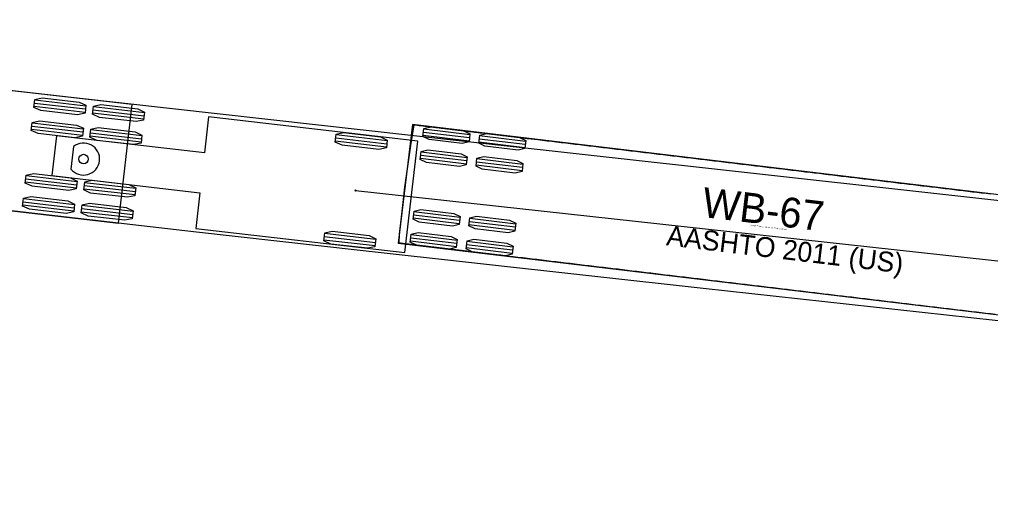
# Model space of a CAD drawing. Extents: x 2175591 to 2194071, y 76570 to 86955.
# Drawn here: x 2192687.6 to 2192756.8, y 86702.6 to 86737.7 of the extents above; entities that cross this region are included whole.
import ezdxf

# ---------------------------------------------------------------- set-up
doc = ezdxf.new("R2010")
doc.units = 0
doc.layers.add('-NOPLT', color=7, linetype='Continuous')
doc.layers.add('C-UTIL-STRM-TEXT', color=7, linetype='Continuous')

msp = doc.modelspace()

# ---------------------------------------------------------------- linework, layer by layer
at = {"layer": '-NOPLT'}
for p, q in [((2192715.586, 86730.244), (2192714.574, 86721.804)), ((2192768.209, 86723.935), (2192715.586, 86730.244)), ((2192719.652, 86729.294), (2192716.375, 86729.687)), ((2192719.679, 86729.522), (2192716.402, 86729.915)), ((2192719.624, 86729.067), (2192716.348, 86729.46)), ((2192723.596, 86728.591), (2192720.319, 86728.984)), ((2192723.623, 86728.818), (2192720.347, 86729.211)), ((2192723.651, 86729.046), (2192720.374, 86729.439)), ((2192719.483, 86727.884), (2192716.206, 86728.277)), ((2192719.428, 86727.429), (2192716.152, 86727.821)), ((2192719.455, 86727.656), (2192716.179, 86728.049)), ((2192723.427, 86727.18), (2192720.15, 86727.573)), ((2192723.454, 86727.408), (2192720.178, 86727.8)), ((2192723.4, 86726.953), (2192720.123, 86727.345)), ((2192718.918, 86723.176), (2192715.642, 86723.569)), ((2192718.945, 86723.403), (2192715.669, 86723.796)), ((2192718.973, 86723.631), (2192715.696, 86724.024)), ((2192722.944, 86723.155), (2192719.668, 86723.548)), ((2192722.89, 86722.7), (2192719.613, 86723.092)), ((2192722.917, 86722.927), (2192719.641, 86723.32)), ((2192718.749, 86721.765), (2192715.473, 86722.158)), ((2192718.776, 86721.993), (2192715.5, 86722.385)), ((2192714.574, 86721.804), (2192767.197, 86715.495)), ((2192718.722, 86721.538), (2192715.445, 86721.93)), ((2192722.693, 86721.061), (2192719.417, 86721.454)), ((2192722.721, 86721.289), (2192719.444, 86721.682)), ((2192722.748, 86721.516), (2192719.471, 86721.909))]:
    msp.add_line(p, q, dxfattribs=at)
for points in [[(2192757.089, 86716.707), (2192756.755, 86716.747), (2192756.421, 86716.787), (2192756.087, 86716.827), (2192755.753, 86716.867), (2192755.42, 86716.907), (2192755.087, 86716.947), (2192754.754, 86716.987), (2192754.421, 86717.027), (2192754.089, 86717.067), (2192753.756, 86717.107), (2192753.425, 86717.146), (2192753.093, 86717.186), (2192752.763, 86717.226), (2192752.432, 86717.265), (2192752.102, 86717.305), (2192751.772, 86717.345), (2192751.442, 86717.384), (2192751.113, 86717.424), (2192750.784, 86717.463), (2192750.455, 86717.502), (2192750.127, 86717.542), (2192749.799, 86717.581), (2192749.471, 86717.62), (2192749.144, 86717.66), (2192748.816, 86717.699), (2192748.489, 86717.738), (2192748.162, 86717.777), (2192747.835, 86717.817), (2192747.508, 86717.856), (2192747.181, 86717.895), (2192746.854, 86717.934), (2192746.527, 86717.973), (2192746.2, 86718.012), (2192745.873, 86718.052), (2192745.546, 86718.091), (2192745.218, 86718.13), (2192744.891, 86718.169), (2192744.563, 86718.209), (2192744.236, 86718.248), (2192743.908, 86718.287), (2192743.58, 86718.327), (2192743.252, 86718.366), (2192742.923, 86718.405), (2192742.594, 86718.445), (2192742.266, 86718.484), (2192741.936, 86718.524), (2192741.607, 86718.563), (2192741.277, 86718.603), (2192740.947, 86718.642), (2192740.616, 86718.682), (2192740.285, 86718.722), (2192739.954, 86718.761), (2192739.622, 86718.801), (2192739.29, 86718.841), (2192738.958, 86718.881), (2192738.624, 86718.921), (2192738.291, 86718.961), (2192737.957, 86719.001), (2192737.623, 86719.041), (2192737.289, 86719.081), (2192736.954, 86719.121), (2192736.618, 86719.161), (2192736.283, 86719.201), (2192735.947, 86719.242), (2192735.611, 86719.282), (2192735.274, 86719.322), (2192734.937, 86719.363), (2192734.6, 86719.403), (2192734.263, 86719.444), (2192733.926, 86719.484), (2192733.588, 86719.524), (2192733.25, 86719.565), (2192732.913, 86719.605), (2192732.575, 86719.646), (2192732.237, 86719.686), (2192731.899, 86719.727), (2192731.561, 86719.768), (2192731.223, 86719.808), (2192730.884, 86719.849), (2192730.546, 86719.889), (2192730.208, 86719.93), (2192729.87, 86719.97), (2192729.532, 86720.011), (2192729.194, 86720.051), (2192728.856, 86720.092), (2192728.517, 86720.132), (2192728.179, 86720.173), (2192727.841, 86720.213), (2192727.503, 86720.254), (2192727.165, 86720.295), (2192726.826, 86720.335), (2192726.488, 86720.376), (2192726.15, 86720.416), (2192725.812, 86720.457), (2192725.473, 86720.497), (2192725.135, 86720.538), (2192724.797, 86720.578), (2192724.458, 86720.619), (2192724.12, 86720.66), (2192723.782, 86720.7), (2192723.443, 86720.741), (2192723.105, 86720.781), (2192722.767, 86720.822), (2192722.155, 86720.895), (2192721.881, 86720.928), (2192721.607, 86720.961), (2192721.333, 86720.994), (2192721.059, 86721.027), (2192720.785, 86721.059), (2192720.511, 86721.092), (2192720.237, 86721.125), (2192719.964, 86721.158), (2192719.69, 86721.191), (2192719.472, 86721.217), (2192719.373, 86721.229), (2192719.275, 86721.24), (2192719.176, 86721.252), (2192719.077, 86721.264), (2192718.978, 86721.276), (2192718.88, 86721.288), (2192718.781, 86721.3), (2192718.682, 86721.311), (2192718.584, 86721.323), (2192718.485, 86721.335), (2192718.386, 86721.347), (2192718.288, 86721.359), (2192718.189, 86721.371), (2192718.09, 86721.382), (2192717.992, 86721.394), (2192717.893, 86721.406), (2192717.794, 86721.418), (2192717.696, 86721.43), (2192717.597, 86721.442), (2192717.498, 86721.453), (2192717.4, 86721.465), (2192717.301, 86721.477), (2192717.203, 86721.489), (2192717.104, 86721.501), (2192717.005, 86721.512), (2192716.907, 86721.524), (2192716.808, 86721.536), (2192716.71, 86721.548), (2192716.611, 86721.56), (2192716.513, 86721.572), (2192716.414, 86721.583), (2192716.316, 86721.595), (2192716.217, 86721.607), (2192716.119, 86721.619), (2192716.02, 86721.631), (2192715.922, 86721.642), (2192715.823, 86721.654), (2192715.725, 86721.666), (2192715.626, 86721.678), (2192715.528, 86721.69), (2192715.429, 86721.701), (2192715.331, 86721.713), (2192715.232, 86721.725), (2192715.134, 86721.737), (2192715.036, 86721.749), (2192714.937, 86721.76), (2192714.839, 86721.772), (2192714.742, 86721.788), (2192714.645, 86721.807), (2192714.661, 86722.435), (2192714.851, 86724.056), (2192714.951, 86724.915), (2192715.052, 86725.774), (2192715.269, 86727.259), (2192715.486, 86728.744), (2192715.703, 86730.229)], [(2192715.703, 86730.229), (2192715.821, 86730.215), (2192715.945, 86730.2), (2192716.073, 86730.185), (2192716.203, 86730.17), (2192716.333, 86730.154), (2192716.463, 86730.138), (2192716.594, 86730.123), (2192716.724, 86730.107), (2192716.855, 86730.091), (2192716.985, 86730.076), (2192717.116, 86730.06), (2192717.247, 86730.044), (2192717.377, 86730.029), (2192717.508, 86730.013), (2192717.639, 86729.997), (2192717.77, 86729.982), (2192717.902, 86729.966), (2192718.033, 86729.95), (2192718.164, 86729.934), (2192718.296, 86729.919), (2192718.427, 86729.903), (2192718.559, 86729.887), (2192718.691, 86729.871), (2192718.822, 86729.856), (2192718.954, 86729.84), (2192719.086, 86729.824), (2192719.218, 86729.808), (2192719.351, 86729.792), (2192719.483, 86729.776), (2192719.615, 86729.76), (2192719.748, 86729.745), (2192719.88, 86729.729), (2192720.013, 86729.713), (2192720.146, 86729.697), (2192720.278, 86729.681), (2192720.411, 86729.665), (2192720.544, 86729.649), (2192720.677, 86729.633), (2192720.811, 86729.617), (2192720.944, 86729.601), (2192721.077, 86729.585), (2192721.211, 86729.569), (2192721.344, 86729.553), (2192721.478, 86729.537), (2192721.612, 86729.521), (2192721.746, 86729.505), (2192721.88, 86729.489), (2192722.014, 86729.473), (2192722.148, 86729.457), (2192722.282, 86729.441), (2192722.416, 86729.425), (2192722.551, 86729.409), (2192722.697, 86729.391), (2192722.849, 86729.373), (2192723.001, 86729.355), (2192723.152, 86729.336), (2192723.303, 86729.318), (2192723.453, 86729.3), (2192723.603, 86729.282), (2192723.753, 86729.264), (2192723.903, 86729.246), (2192724.052, 86729.229), (2192724.531, 86729.171), (2192724.862, 86729.132), (2192725.192, 86729.092), (2192725.523, 86729.052), (2192725.853, 86729.013), (2192726.184, 86728.973), (2192726.515, 86728.933), (2192726.845, 86728.894), (2192727.176, 86728.854), (2192727.506, 86728.814), (2192727.837, 86728.775), (2192728.168, 86728.735), (2192728.498, 86728.696), (2192728.829, 86728.656), (2192729.159, 86728.616), (2192729.49, 86728.577), (2192729.82, 86728.537), (2192730.15, 86728.497), (2192730.481, 86728.458), (2192730.811, 86728.418), (2192731.142, 86728.379), (2192731.472, 86728.339), (2192731.803, 86728.299), (2192732.133, 86728.26), (2192732.463, 86728.22), (2192732.794, 86728.181), (2192733.124, 86728.141), (2192733.455, 86728.101), (2192733.785, 86728.062), (2192734.115, 86728.022), (2192734.445, 86727.983), (2192734.775, 86727.943), (2192735.105, 86727.903), (2192735.435, 86727.864), (2192735.765, 86727.824), (2192736.094, 86727.785), (2192736.424, 86727.745), (2192736.753, 86727.706), (2192737.082, 86727.667), (2192737.41, 86727.627), (2192737.739, 86727.588), (2192738.067, 86727.548), (2192738.394, 86727.509), (2192738.721, 86727.47), (2192739.048, 86727.431), (2192739.375, 86727.392), (2192739.701, 86727.352), (2192740.027, 86727.313), (2192740.352, 86727.274), (2192740.677, 86727.235), (2192741.002, 86727.197), (2192741.326, 86727.158), (2192741.65, 86727.119), (2192741.973, 86727.08), (2192742.296, 86727.041), (2192742.619, 86727.003), (2192742.941, 86726.964), (2192743.263, 86726.925), (2192743.585, 86726.887), (2192743.906, 86726.848), (2192744.227, 86726.81), (2192744.548, 86726.771), (2192744.869, 86726.733), (2192745.19, 86726.694), (2192745.51, 86726.656), (2192745.83, 86726.618), (2192746.15, 86726.579), (2192746.47, 86726.541), (2192746.79, 86726.503), (2192747.11, 86726.464), (2192747.429, 86726.426), (2192747.749, 86726.388), (2192748.068, 86726.349), (2192748.388, 86726.311), (2192748.707, 86726.273), (2192749.027, 86726.234), (2192749.347, 86726.196), (2192749.666, 86726.158), (2192749.986, 86726.119), (2192750.306, 86726.081), (2192750.626, 86726.043), (2192750.946, 86726.004), (2192751.267, 86725.966), (2192751.588, 86725.927), (2192751.909, 86725.889), (2192752.23, 86725.85), (2192752.552, 86725.812), (2192752.874, 86725.773), (2192753.196, 86725.735), (2192753.519, 86725.696), (2192753.842, 86725.657), (2192754.165, 86725.618), (2192754.489, 86725.58), (2192754.813, 86725.541), (2192755.138, 86725.502), (2192755.463, 86725.463), (2192755.788, 86725.424), (2192756.113, 86725.385), (2192756.439, 86725.346), (2192756.765, 86725.307)]]:
    msp.add_lwpolyline(points, dxfattribs=at)
for points in [[(2192719.686, 86729.578), (2192719.618, 86729.011), (2192719.138, 86728.894), (2192716.779, 86729.177), (2192716.341, 86729.403), (2192716.409, 86729.971), (2192716.888, 86730.087), (2192719.248, 86729.805)], [(2192723.657, 86729.102), (2192723.589, 86728.534), (2192723.11, 86728.418), (2192720.751, 86728.701), (2192720.313, 86728.927), (2192720.381, 86729.495), (2192720.86, 86729.611), (2192723.219, 86729.328)], [(2192719.489, 86727.94), (2192719.421, 86727.372), (2192718.942, 86727.256), (2192716.583, 86727.539), (2192716.145, 86727.765), (2192716.213, 86728.333), (2192716.692, 86728.449), (2192719.051, 86728.166)], [(2192723.461, 86727.464), (2192723.393, 86726.896), (2192722.914, 86726.78), (2192720.555, 86727.063), (2192720.116, 86727.289), (2192720.184, 86727.857), (2192720.664, 86727.973), (2192723.023, 86727.69)], [(2192718.98, 86723.687), (2192718.911, 86723.119), (2192718.432, 86723.003), (2192716.073, 86723.286), (2192715.635, 86723.512), (2192715.703, 86724.08), (2192716.182, 86724.196), (2192718.541, 86723.913)], [(2192722.951, 86723.211), (2192722.883, 86722.643), (2192722.404, 86722.527), (2192720.045, 86722.81), (2192719.606, 86723.036), (2192719.675, 86723.604), (2192720.154, 86723.72), (2192722.513, 86723.437)], [(2192718.783, 86722.049), (2192718.715, 86721.481), (2192718.236, 86721.365), (2192715.877, 86721.648), (2192715.439, 86721.874), (2192715.507, 86722.442), (2192715.986, 86722.558), (2192718.345, 86722.275)], [(2192722.755, 86721.573), (2192722.687, 86721.005), (2192722.207, 86720.889), (2192719.848, 86721.172), (2192719.41, 86721.398), (2192719.478, 86721.966), (2192719.957, 86722.082), (2192722.316, 86721.799)]]:
    msp.add_lwpolyline(points, close=True, dxfattribs=at)
at = {"layer": 'C-UTIL-STRM-TEXT'}
for p, q in [((2192695.635, 86731.665), (2192642.984, 86737.74)), ((2192692.308, 86731.336), (2192688.666, 86731.756)), ((2192692.335, 86731.563), (2192688.692, 86731.984)), ((2192692.282, 86731.108), (2192688.64, 86731.528)), ((2192696.454, 86730.627), (2192692.812, 86731.047)), ((2192696.481, 86730.854), (2192692.838, 86731.275)), ((2192696.507, 86731.082), (2192692.864, 86731.502)), ((2192694.661, 86723.221), (2192695.635, 86731.665)), ((2192695.635, 86731.665), (2192695.635, 86731.665)), ((2192692.146, 86729.924), (2192688.503, 86730.345)), ((2192701.07, 86730.786), (2192700.776, 86728.237)), ((2192715.971, 86729.067), (2192701.07, 86730.786)), ((2192692.093, 86729.469), (2192688.451, 86729.889)), ((2192692.119, 86729.697), (2192688.477, 86730.117)), ((2192696.292, 86729.215), (2192692.649, 86729.636)), ((2192696.318, 86729.443), (2192692.675, 86729.863)), ((2192642.01, 86729.296), (2192694.661, 86723.221)), ((2192690.245, 86729.452), (2192689.917, 86726.604)), ((2192700.776, 86728.237), (2192690.245, 86729.452)), ((2192696.265, 86728.988), (2192692.623, 86729.408)), ((2192713.74, 86728.633), (2192710.097, 86729.053)), ((2192713.766, 86728.86), (2192710.124, 86729.28)), ((2192713.792, 86729.088), (2192710.15, 86729.508)), ((2192715.054, 86721.12), (2192715.971, 86729.067)), ((2192715.971, 86729.067), (2192715.971, 86729.067)), ((2192691.457, 86728.682), (2192691.272, 86727.077)), ((2192691.686, 86725.938), (2192688.043, 86726.359)), ((2192691.712, 86726.166), (2192688.069, 86726.586)), ((2192689.917, 86726.604), (2192700.447, 86725.389)), ((2192691.659, 86725.711), (2192688.017, 86726.131)), ((2192695.832, 86725.229), (2192692.189, 86725.65)), ((2192695.858, 86725.457), (2192692.215, 86725.877)), ((2192695.884, 86725.685), (2192692.242, 86726.105)), ((2192711.539, 86725.552), (2192896.881, 86705.206)), ((2192691.523, 86724.527), (2192687.88, 86724.947)), ((2192700.447, 86725.389), (2192700.153, 86722.839)), ((2192691.47, 86724.072), (2192687.828, 86724.492)), ((2192691.497, 86724.299), (2192687.854, 86724.719)), ((2192695.669, 86723.818), (2192692.026, 86724.238)), ((2192695.695, 86724.045), (2192692.053, 86724.466)), ((2192695.643, 86723.59), (2192692, 86724.01)), ((2192700.153, 86722.839), (2192715.054, 86721.12)), ((2192712.954, 86721.824), (2192709.312, 86722.244)), ((2192712.98, 86722.051), (2192709.338, 86722.471)), ((2192712.928, 86721.596), (2192709.285, 86722.016))]:
    msp.add_line(p, q, dxfattribs=at)
for points in [[(2192881.867, 86702.593), (2192736.29, 86718.562), (2192712.089, 86721.246), (2192699.991, 86722.61), (2192642.01, 86729.296), (2192642.984, 86737.74), (2192643.16, 86737.719), (2192643.16, 86737.719)], [(2192643.16, 86737.719), (2192667.317, 86734.938), (2192691.501, 86732.186), (2192715.689, 86729.468), (2192764.077, 86724.094)]]:
    msp.add_lwpolyline(points, dxfattribs=at)
for points in [[(2192692.341, 86731.62), (2192692.276, 86731.052), (2192691.746, 86730.939), (2192689.123, 86731.242), (2192688.633, 86731.472), (2192688.699, 86732.04), (2192689.228, 86732.153), (2192691.851, 86731.85)], [(2192696.513, 86731.139), (2192696.448, 86730.57), (2192695.918, 86730.458), (2192693.296, 86730.761), (2192692.805, 86730.991), (2192692.871, 86731.559), (2192693.401, 86731.671), (2192696.023, 86731.369)], [(2192692.152, 86729.981), (2192692.086, 86729.413), (2192691.557, 86729.3), (2192688.934, 86729.603), (2192688.444, 86729.833), (2192688.51, 86730.401), (2192689.039, 86730.513), (2192691.662, 86730.211)], [(2192696.324, 86729.499), (2192696.259, 86728.931), (2192695.729, 86728.819), (2192693.107, 86729.121), (2192692.616, 86729.351), (2192692.682, 86729.92), (2192693.212, 86730.032), (2192695.834, 86729.729)], [(2192713.799, 86729.144), (2192713.733, 86728.576), (2192713.204, 86728.464), (2192710.581, 86728.766), (2192710.091, 86728.996), (2192710.156, 86729.565), (2192710.686, 86729.677), (2192713.309, 86729.374)], [(2192691.718, 86726.222), (2192691.653, 86725.654), (2192691.123, 86725.542), (2192688.501, 86725.844), (2192688.01, 86726.074), (2192688.076, 86726.643), (2192688.606, 86726.755), (2192691.228, 86726.452)], [(2192695.891, 86725.741), (2192695.825, 86725.173), (2192695.295, 86725.06), (2192692.673, 86725.363), (2192692.183, 86725.593), (2192692.248, 86726.161), (2192692.778, 86726.274), (2192695.401, 86725.971)], [(2192691.529, 86724.583), (2192691.464, 86724.015), (2192690.934, 86723.903), (2192688.311, 86724.205), (2192687.821, 86724.435), (2192687.887, 86725.004), (2192688.417, 86725.116), (2192691.039, 86724.813)], [(2192695.702, 86724.102), (2192695.636, 86723.534), (2192695.106, 86723.421), (2192692.484, 86723.724), (2192691.994, 86723.954), (2192692.059, 86724.522), (2192692.589, 86724.635), (2192695.211, 86724.332)], [(2192712.987, 86722.108), (2192712.921, 86721.539), (2192712.392, 86721.427), (2192709.769, 86721.73), (2192709.279, 86721.96), (2192709.344, 86722.528), (2192709.874, 86722.64), (2192712.497, 86722.338)]]:
    msp.add_lwpolyline(points, close=True, dxfattribs=at)
for centre, radius in [((2192692.167, 86727.787), 0.34), ((2192711.539, 86725.552), 0.0417)]:
    msp.add_circle(centre, radius, dxfattribs=at)
msp.add_arc((2192692.167, 86727.787), 1.143, 218.41874, 128.41874, dxfattribs=at)

# ---------------------------------------------------------------- texts
at = {"layer": '-NOPLT'}
for s, height, p in [('WB-67', 2.125, (2192736.137, 86723.671)), ('AASHTO 2011 (US)', 1.41667, (2192733.628, 86721.653)), ('(c) 2022 Transoft Solutions, Inc. All rights reserved.', 0.085, (2192739.658, 86723.034))]:
    msp.add_text(s, height=height, rotation=353.16366, dxfattribs=at).set_placement(p)

doc.saveas('drawing.dxf')
